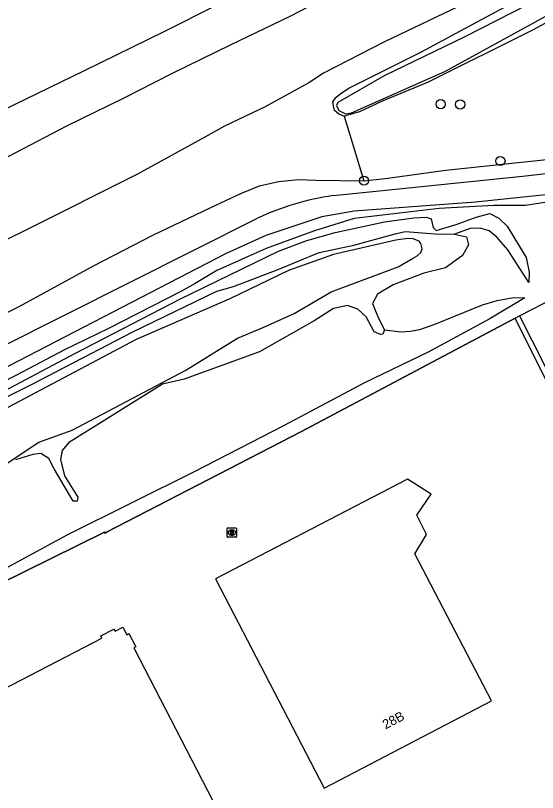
# Model space of a CAD drawing. Extents: x 156651 to 158072, y 387631 to 388990.
# Drawn here: x 157099.8 to 157155.2, y 388391.5 to 388473.9 of the extents above; entities that cross this region are included whole.
import ezdxf

# ---------------------------------------------------------------- set-up
doc = ezdxf.new("R2010")
doc.units = 0
for name, color, linetype in [('IMGEO_Berm_groen', 7, 'Continuous'), ('IMGEO_Boom', 7, 'Continuous'), ('IMGEO_Grasland_overig', 7, 'Continuous'), ('IMGEO_Groenvoorziening', 7, 'Continuous'), ('IMGEO_Loofbos', 7, 'Continuous'), ('IMGEO_Meer_plas_ven_vijver', 7, 'Continuous'), ('IMGEO_Muur', 7, 'Continuous'), ('IMGEO_Pand', 7, 'Continuous'), ('IMGEO_Pand_nummerreeks', 7, 'Continuous'), ('IMGEO_Rijbaan_autosnelweg', 7, 'Continuous'), ('IMGEO_Rijbaan_lokaal_gesloten', 7, 'Continuous'), ('IMGEO_Rioolput', 7, 'Continuous'), ('IMGEO_Waterloop', 7, 'Continuous')]:
    doc.layers.add(name, color=color, linetype=linetype)

msp = doc.modelspace()

# ---------------------------------------------------------------- linework, layer by layer
at = {"layer": 'IMGEO_Berm_groen'}
msp.add_lwpolyline([(157033.612, 388428.043), (157048.162, 388434.79), (157060.456, 388440.581), (157064.172, 388442.303), (157069.84, 388444.866), (157076.701, 388447.975), (157081.399, 388450.321), (157085.968, 388452.381), (157088.905, 388453.969), (157093.57, 388456.137), (157099.849, 388459.385), (157105.262, 388462.221), (157111.245, 388465.123), (157116.377, 388467.751), (157122.623, 388470.789), (157128.997, 388473.856), (157140.097, 388479.658)], dxfattribs=at)
at = {"layer": 'IMGEO_Boom'}
for centre in [(157144.908, 388464.511), (157146.968, 388464.474), (157151.238, 388458.481), (157136.769, 388456.391)]:
    msp.add_circle(centre, 0.489, dxfattribs=at)
at = {"layer": 'IMGEO_Grasland_overig'}
for points in [[(157147.55, 388475.198), (157138.937, 388471.102), (157132.491, 388467.79), (157130.925, 388466.749), (157126.206, 388464.167), (157121.968, 388462.161), (157119.871, 388461.006), (157112.745, 388457.095), (157100.986, 388451.192), (157089.741, 388445.654), (157078.331, 388439.91), (157069.742, 388435.653), (157059.626, 388430.697), (157049.387, 388425.652), (157038.442, 388420.38)], [(157152.544, 388475.241), (157142.768, 388469.987), (157135.181, 388466.182), (157134.318, 388465.581), (157133.712, 388465.154), (157133.568, 388464.957), (157133.42, 388464.753), (157133.586, 388463.938), (157134.09, 388463.485), (157134.65, 388463.237)], [(157044.075, 388415.794), (157052.029, 388420.021), (157059.876, 388423.419), (157066.273, 388426.445), (157075.497, 388431.156), (157083.188, 388434.612), (157090.495, 388438.412), (157092.585, 388439.369), (157092.718, 388439.787), (157093.155, 388439.825), (157093.629, 388439.782), (157100.178, 388443.04), (157108.164, 388447.411), (157114.382, 388450.614), (157120.444, 388453.52), (157123.782, 388455.081), (157125.696, 388455.86), (157127.69, 388456.319), (157129.834, 388456.523), (157131.691, 388456.433), (157136.769, 388456.391)]]:
    msp.add_lwpolyline(points, dxfattribs=at)
at = {"layer": 'IMGEO_Groenvoorziening'}
for points in [[(157259.041, 388475.526), (157251.013, 388473.012), (157247.626, 388472.118), (157232.053, 388468.421), (157214.697, 388465.304), (157192.104, 388460.339), (157177.394, 388457.523), (157167.178, 388455.453), (157158.68, 388454.488), (157153.9, 388453.762), (157150.53, 388453.743), (157144.729, 388453.453), (157135.723, 388452.372), (157131.52, 388451.074), (157126.398, 388449.193), (157121.147, 388446.875), (157118.863, 388445.501), (157117.424, 388444.679), (157109.676, 388440.71), (157105.007, 388438.442), (157099.835, 388435.717), (157085.053, 388428.203)], [(157096.872, 388433.194), (157106.116, 388438.075), (157117.316, 388443.852), (157127.701, 388448.931), (157130.721, 388450.055), (157133.705, 388450.902), (157138.955, 388452.042), (157142.069, 388452.463), (157143.377, 388452.51), (157143.912, 388452.333), (157144.105, 388451.417), (157144.437, 388451.115), (157146.544, 388451.755), (157148.655, 388452.527), (157150.105, 388452.9), (157151.066, 388452.431), (157151.973, 388451.582), (157153.983, 388448.255), (157154.273, 388446.702), (157154.261, 388445.594), (157152.019, 388449.074), (157150.864, 388450.393), (157150.042, 388451.055), (157149.102, 388451.338), (157148.046, 388451.308), (157146.364, 388450.732)], [(157092.727, 388430.42), (157101.584, 388434.8), (157112.263, 388440.371), (157121.157, 388444.67), (157122.941, 388445.163), (157127.55, 388446.95), (157132.018, 388448.768), (157135.682, 388449.54), (157140.078, 388450.745), (157141.148, 388451.002), (157144.307, 388450.763), (157146.364, 388450.732)], [(157146.364, 388450.732), (157147.66, 388450.45), (157147.855, 388449.599), (157147.209, 388448.461), (157145.41, 388447.15), (157143.108, 388446.583), (157139.847, 388445.349), (157138.191, 388444.363), (157137.669, 388443.379), (157138.29, 388441.88), (157138.957, 388440.564)], [(157138.957, 388440.564), (157140.678, 388440.347), (157141.683, 388440.418), (157142.693, 388440.621), (157144.402, 388441.209), (157149.351, 388443.216), (157150.912, 388443.703), (157152.624, 388444.001), (157153.836, 388443.973), (157150.039, 388441.715), (157143.573, 388438.203), (157136.826, 388434.951), (157128.24, 388430.404), (157118.826, 388425.542), (157105.325, 388418.841), (157094.625, 388413.034)], [(157138.957, 388440.564), (157138.771, 388440.122), (157138.505, 388440.065), (157137.843, 388440.378), (157136.987, 388441.964), (157136.131, 388442.772), (157135.01, 388443.166), (157133.547, 388442.821), (157131.472, 388441.546), (157125.686, 388438.249), (157117.711, 388435.342), (157115.397, 388434.802), (157105.435, 388428.586), (157104.761, 388427.792), (157104.583, 388426.835), (157104.998, 388425.079), (157106.412, 388422.841), (157106.357, 388422.394), (157105.935, 388422.395), (157103.903, 388425.842), (157103.346, 388426.917), (157102.507, 388427.473), (157101.646, 388427.371), (157099.806, 388426.787)], [(156865.154, 388270.87), (156882.486, 388283.2), (156947.52, 388329.05), (156961.889, 388339.164), (156969.373, 388344.277), (156978.86, 388351.247), (156984.416, 388354.408), (157034.33, 388380.441), (157049.058, 388388.287), (157064.028, 388395.888), (157078.365, 388403.523), (157095.099, 388412.158), (157109.228, 388419.114), (157109.331, 388419.031), (157109.473, 388419.105), (157130.067, 388429.759), (157152.815, 388441.828)]]:
    msp.add_lwpolyline(points, dxfattribs=at)
at = {"layer": 'IMGEO_Loofbos'}
for points in [[(157240.152, 388483.009), (157239.613, 388482.435), (157238.961, 388482.106), (157238.018, 388481.763), (157237.251, 388481.946), (157236.646, 388482.293), (157234.605, 388485.191), (157230.13, 388492.294), (157221.954, 388506.436), (157221.613, 388506.726), (157221.268, 388506.894), (157220.638, 388506.843), (157213.252, 388502.923), (157184.544, 388488.01), (157167.521, 388479.375), (157154.701, 388472.398), (157143.573, 388466.851), (157138.632, 388464.794), (157136.31, 388463.7), (157134.65, 388463.237)], [(157136.769, 388456.391), (157139.032, 388456.617), (157145.462, 388457.518), (157158.145, 388458.851), (157168.809, 388460.57), (157199.2, 388466.547), (157211.43, 388469.283), (157223.056, 388472.1), (157229.673, 388473.907), (157236.096, 388475.028)], [(157134.65, 388463.237), (157136.769, 388456.391)]]:
    msp.add_lwpolyline(points, dxfattribs=at)
at = {"layer": 'IMGEO_Meer_plas_ven_vijver'}
msp.add_lwpolyline([(157098.153, 388425.939), (157102.27, 388428.671), (157105.81, 388429.948), (157117.855, 388436.303), (157123.34, 388439.698), (157126.131, 388440.871), (157129.366, 388442.307), (157133.302, 388444.603), (157140.407, 388447.247), (157141.913, 388448.128), (157142.406, 388448.439), (157142.785, 388448.791), (157142.936, 388449.181), (157142.797, 388449.717), (157142.609, 388449.959), (157141.969, 388450.229), (157141.432, 388450.264), (157140.154, 388450.085), (157133.533, 388448.567), (157128.762, 388446.878), (157122.535, 388443.874), (157112.6, 388439.565), (157079.407, 388421.998)], dxfattribs=at)
at = {"layer": 'IMGEO_Muur'}
for points in [[(157152.815, 388441.828), (157130.067, 388429.759), (157109.473, 388419.105)], [(157152.815, 388441.828), (157153.258, 388442.056)], [(157172.287, 388404.528), (157171.861, 388404.266), (157168.584, 388410.695), (157159.474, 388428.962), (157159.283, 388428.837), (157152.815, 388441.828)], [(157153.258, 388442.056), (157172.287, 388404.528)], [(157109.473, 388419.105), (157109.331, 388419.031), (157109.228, 388419.114), (157095.099, 388412.158), (157078.365, 388403.523), (157064.028, 388395.888), (157049.058, 388388.287), (157034.33, 388380.441), (156984.416, 388354.408), (156978.86, 388351.247), (156969.373, 388344.277), (156961.889, 388339.164), (156947.52, 388329.05), (156882.486, 388283.2), (156865.154, 388270.87)]]:
    msp.add_lwpolyline(points, dxfattribs=at)
at = {"layer": 'IMGEO_Pand'}
for points in [[(157150.297, 388401.222), (157142.148, 388416.839), (157143.398, 388418.865), (157142.363, 388420.934), (157143.88, 388423.145), (157141.369, 388424.74), (157121.02, 388414.182), (157132.558, 388391.965), (157150.297, 388401.222)], [(157089.011, 388397.56), (157108.974, 388407.898), (157108.871, 388408.12), (157110.249, 388408.852), (157110.388, 388408.636), (157111.207, 388409.061), (157111.602, 388408.232), (157111.843, 388408.367), (157112.573, 388406.979), (157112.346, 388406.86), (157125.202, 388382.016)]]:
    msp.add_lwpolyline(points, dxfattribs=at)
at = {"layer": 'IMGEO_Rijbaan_autosnelweg'}
msp.add_lwpolyline([(157183.298, 388507.707), (157176.26, 388503.877), (157160.502, 388495.465), (157143.493, 388486.539), (157126.489, 388477.734), (157115.614, 388472.203), (157107.094, 388468.042), (157098.434, 388463.834), (157088.311, 388458.89), (157085.419, 388457.485)], dxfattribs=at)
at = {"layer": 'IMGEO_Rijbaan_lokaal_gesloten'}
msp.add_lwpolyline([(157153.258, 388442.056), (157157.115, 388444.038)], dxfattribs=at)
at = {"layer": 'IMGEO_Rioolput'}
for p, q in [((157122.247, 388418.651), (157122.247, 388419.503)), ((157122.322, 388419.577), (157123.174, 388419.577)), ((157122.735, 388419.357), (157122.76, 388419.357)), ((157123.248, 388419.503), (157123.248, 388418.651)), ((157123.174, 388418.577), (157122.322, 388418.577)), ((157122.758, 388418.797), (157122.733, 388418.797))]:
    msp.add_line(p, q, dxfattribs=at)
for points in [[(157122.247, 388418.651), (157122.247, 388419.503)], [(157122.322, 388419.577), (157123.174, 388419.577)], [(157122.836, 388419.275), (157122.584, 388419.277), (157122.584, 388418.877)], [(157122.584, 388418.877), (157122.708, 388418.877), (157122.708, 388419.039), (157122.719, 388419.039)], [(157122.762, 388419.196), (157122.708, 388419.196), (157122.708, 388419.115)], [(157122.708, 388419.115), (157122.76, 388419.115)], [(157122.766, 388419.01), (157122.837, 388418.877), (157122.977, 388418.877), (157122.912, 388419.003)], [(157123.248, 388419.503), (157123.248, 388418.651)], [(157123.174, 388418.577), (157122.322, 388418.577)]]:
    msp.add_lwpolyline(points, dxfattribs=at)
for centre, radius, start, end in [((157122.324, 388419.501), 0.0765, 91.55205, 178.44795), ((157122.324, 388419.501), 0.0765, 91.55205, 178.44795), ((157122.718, 388418.986), 0.0533, 26.02933, 88.69889), ((157122.744, 388419.304), 0.19, 274.7715, 282.96867), ((157122.768, 388419.1), 0.0964, 77.00612, 93.18647), ((157122.782, 388419.157), 0.0378, 276.66336, 79.67722), ((157122.835, 388419.165), 0.109, 350.36119, 89.41601), ((157122.833, 388419.165), 0.112, 277.58423, 350.98172), ((157122.817, 388418.95), 0.108, 29.51342, 73.79051), ((157123.172, 388419.501), 0.0765, 1.55205, 88.44795), ((157123.172, 388419.501), 0.0765, 1.55205, 88.44795), ((157122.324, 388418.653), 0.0765, 181.55205, 268.44795), ((157122.324, 388418.653), 0.0765, 181.55205, 268.44795), ((157123.172, 388418.653), 0.0765, 271.55205, 358.44795), ((157123.172, 388418.653), 0.0765, 271.55205, 358.44795)]:
    msp.add_arc(centre, radius, start, end, dxfattribs=at)
for centre, major_axis, ratio, start_param, end_param in [((157122.734, 388419.077), (-0.387, 0.002), 0.722429, 4.712389, 7.853982), ((157122.759, 388419.077), (-0.39, 0.002), 0.717154, 1.570796, 4.712389)]:
    msp.add_ellipse(centre, major_axis=major_axis, ratio=ratio, start_param=start_param, end_param=end_param, dxfattribs=at)
at = {"layer": 'IMGEO_Waterloop'}
for points in [[(157133.487, 388454.807), (157137.347, 388455.218), (157153.569, 388456.86), (157162.891, 388457.928), (157183.713, 388461.706), (157211.433, 388467.661), (157226.834, 388470.947), (157245.191, 388475.382), (157258.292, 388478.914), (157268.928, 388482.363), (157286.012, 388488.524), (157291.433, 388490.7), (157301.618, 388494.355), (157316.854, 388498.873), (157327.532, 388501.542), (157364.411, 388510.864)], [(157182.28, 388489.466), (157147.454, 388471.63), (157138.913, 388467.507), (157133.994, 388464.687), (157133.838, 388464.378), (157134.086, 388463.838), (157134.823, 388463.462), (157135.444, 388463.599), (157143.841, 388467.296), (157145.335, 388467.954), (157163.344, 388477.874)], [(157255.731, 388475.572), (157234.027, 388469.802), (157227.415, 388468.467), (157206.207, 388464.016), (157191.752, 388460.813), (157177.086, 388457.974), (157166.166, 388455.967), (157148.589, 388454.119), (157135.715, 388453.174), (157132.285, 388452.558), (157126.351, 388450.567), (157122.08, 388448.636), (157095.057, 388434.673), (157062.942, 388418.862), (157022.696, 388398.411), (156983.805, 388379.684), (156952.388, 388365.844), (156912.717, 388349.17), (156867.85, 388330.813), (156853.805, 388325.372), (156843.628, 388321.456), (156840.606, 388320.217), (156839.963, 388319.697)], [(156860.992, 388280.793), (156849.649, 388298.939), (156841.494, 388312.579), (156839.705, 388315.711), (156837.036, 388320.289), (156836.88, 388321.296), (156837.183, 388321.85), (156837.84, 388322.548), (156839.051, 388323.062), (156841.721, 388323.595), (156843.918, 388323.76), (156875.129, 388336.491), (156912.337, 388351.809), (156949.175, 388367.374), (156982.809, 388381.994), (157017.47, 388398.462), (157045.561, 388412.795), (157068.764, 388424.088), (157098.168, 388438.708), (157125.478, 388452.425)]]:
    msp.add_lwpolyline(points, dxfattribs=at)
msp.add_arc((157137.608, 388426.294), 28.809, 98.22495, 114.90162, dxfattribs=at)

# ---------------------------------------------------------------- texts
at = {"layer": 'IMGEO_Pand_nummerreeks'}
msp.add_text('28B', height=1, rotation=27.55756, dxfattribs=at).set_placement((157139.059, 388398.2))

doc.saveas('drawing.dxf')
